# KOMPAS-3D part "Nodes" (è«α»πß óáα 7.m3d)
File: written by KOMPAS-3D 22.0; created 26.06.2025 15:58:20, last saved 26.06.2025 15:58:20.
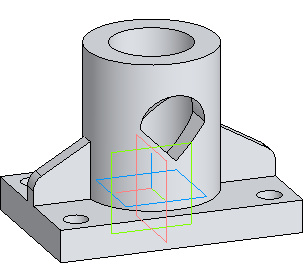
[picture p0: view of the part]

Document properties: Автор: Helen; Полное имя файла: D:\MY\WORK\MPEI\ППЭ_2025-2026\Варианты\Вар 7 СБ\Корпус вар 7.m3d

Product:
- Part/product: Nodes

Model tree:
1. Операция без истории:1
